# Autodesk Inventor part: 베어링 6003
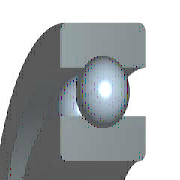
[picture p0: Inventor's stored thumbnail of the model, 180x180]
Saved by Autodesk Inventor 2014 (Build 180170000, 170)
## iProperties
IsCustomPart: 1
Created: 2009-02
Part Number: 베어링 6003
Material: 강, 연강
Description: 깊은 그루브 볼 베어링
Document SubType Name: Modeling
Standard: KS B 2023
Designer: 한국산업디자인학원
Standards Organization: KS
Language: ko-KR
Size Designation: 6003 - 17 x 35 x 10
Categories: <MemberInstance><Categories><Category DisplayName="샤프트 부품" InternalName="7f7aeb1f-a693-4053-b835-cee3144e0d98" Mnemonic="SHFT"><Category DisplayName="베어링" Inter
Density: 1 g/cm^3
Appearance: 강철
Author: 한국산업디자인학원
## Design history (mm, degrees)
sketch "스케치" dims "d0" = 4.68 (= -0.26 x WD + 0.26 x BD)
  geometry: L1 (2.66, 13)-(7.34, 13); L2 (5, 13)-(5, 10.66); L3 (5, 13)-(5, 15.34); L4 (3.261, 11.434)-(0, 11.434); L5 (0, 8.5)-(10, 8.5); L6 (3.261, 14.566)-(0, 14.566); L7 (0, 17.5)-(10, 17.5); L8 (10, 8.5)-(10, 11.434); L9 (6.739, 11.434)-(10, 11.434); L10 (6.739, 14.566)-(10, 14.566); L11 (10, 17.5)-(10, 14.566); L12 (-1.4, 0)-(8.4, 0) reference; L13 (0, -0.3)-(0, 5.3) reference
  constraints: 22 end point, 4 point on line, 2 collinear, 2 perpendicular, 2 symmetric about line, 1 midpoint, 1 parallel, 14 other
  dimensions: "d9" = 17 diameter of L5 L12 (= WD); "d11" = 35 diameter of L7 L12 (= BD); "d12" = 10 distance between parallel lines of L8 L13 (= KB); "d13" = 22.868 diameter of L9 L12 (= 0.326 x BD + 0.674 x WD)
revolve "본체" stored, may be unused: angle "d6" = 90 deg
revolve "볼" stored, may be unused: angle "d7" = 90 deg
pattern_circular "IDS_ARRAYBALL[SIMPL:T]" dims angle "d3" = 360 deg
body "Solid1"
fillet "모깎기1" dims "d1" = 0.3 (= KRS)
other parameters: "WD" = 17 [user parameter; used in 5 equation terms], "BD" = 35 [user parameter; used in 5 equation terms], "KB" = 10 [user parameter; used in 1 equation term], "KRS" = 0.3 [user parameter; used in 1 equation term], "d4" = 0, "d5" = 0, "d8" = 0, "d14" = 0, "d15" = 0, "BBA" = 0 [user parameter], "BC0" = 3250000 [user parameter], "BC" = 6050000 [user parameter], "BR" = 17.5 (= 0.5 x BD) [user parameter], "WR" = 8.5 (= 0.5 x WD) [user parameter]
